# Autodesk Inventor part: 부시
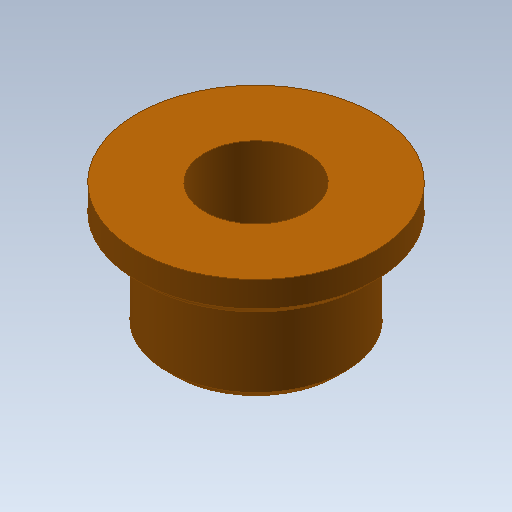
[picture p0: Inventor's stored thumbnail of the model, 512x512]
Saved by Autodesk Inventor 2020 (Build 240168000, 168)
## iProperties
Created: 2016-02
Part Number: 부시
Material: 강철, 연강
Document SubType Name: Modeling
Designer: test
Density: 1 g/cm^3
Appearance: 주황색
Author: test
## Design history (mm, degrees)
sketch "스케치1"
  geometry: C1 r 14 at (0, 0); C2 r 10.5 at (0, 0); 1 further point
  constraints: 2 centre point, 2 coincident
  dimensions: "d0" = 28 diameter of C1; "d1" = 21 diameter of C2
extrude "돌출1" new body sketch "스케치1" distance "d2" = 4; taper "d3" = 0 deg
extrude "돌출2" join sketch "스케치1" distance "d4" = 11; taper "d5" = 0 deg
hole "구멍1" diameter "d8" = 12; stored, may be unused: countersink angle "d12" = 90 deg, drill point angle "d14" = 118 deg; dims "d6" = 10, "d7" = 10, "d9" = 6, "d10" = 4, "d11" = 2, "d13" = 8
chamfer "모따기1" distance "d15" = 1; stored, may be unused: second distance "d16" = 2, angle "d17" = 45 deg
chamfer "모따기2" distance "d18" = 1; stored, may be unused: second distance "d19" = 2, angle "d20" = 45 deg
node "솔리드1"
